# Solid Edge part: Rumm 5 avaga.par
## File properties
Title: Wasserdichte Bremsnabe
Author: Kadik
Comments: F200 112x5 - M12x1,5
Template: Normál.par
Last saved by: Kadik
Revision: 34
Application: Solid Edge
Material: GG25 (HB 195-225)
Category: 6A2267.001
Density: 7850,000 kg/m^3
Accuracy: 0,99
Document Number: 6A5139
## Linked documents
6A0073.001.par
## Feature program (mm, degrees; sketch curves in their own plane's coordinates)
part copy "unnamed PartCopy 1"
sketch for "unnamed RevolvedCutout 1" plane through (0, 0, 0) normal (0, -1, 0) x-axis (1, 0, 0)
  line (84.5, 117.2106) -> (84.5, 100)
  line (30.5, 100) -> (84.5, 100)
  line (30.5, 100) -> (20.5, 82.6795)
  line (20.5, 82.6795) -> (34.9125, 82.6795)
revolve "unnamed RevolvedCutout 1" cut full turn 360 deg
sketch for "unnamed RevolvedCutout 2" plane through (0, 0, 0) normal (0, -1, 0) x-axis (1, 0, 0)
  line (52, 32) -> (-14.4342, 32)
  line (52, 28) -> (52, 32)
  line (61, 28) -> (52, 28)
  line (61, 48.9983) -> (61, 28)
  line (61, 48.9983) -> (64.6809, 48.9983)
revolve "unnamed RevolvedCutout 2" cut full turn 360 deg
sketch for "unnamed RevolvedCutout 3" plane through (0, 0, 0) normal (0, -1, 0) x-axis (1, 0, 0)
  line (52, 32.2714) -> (50, 32)
  line (52, 32.2714) -> (52, 28)
revolve "unnamed RevolvedCutout 3" cut full turn 360 deg
sketch for "unnamed RevolvedCutout 4" plane through (0, 0, 0) normal (0, -1, 0) x-axis (1, 0, 0)
  line (0, 0) -> (0, 0)
  line (11, 32) -> (11, 33.3319)
  arc centre (11.5, 33.3319) radius 0.5 from (11, 33.3319) to (11.671, 33.8017) cw
  line (12.5, 33.5) -> (11.671, 33.8017)
  line (12.5, 33.5) -> (13.65, 33.5)
  line (13.65, 33.5) -> (14.479, 33.8017)
  arc centre (14.65, 33.3319) radius 0.5 from (14.479, 33.8017) to (15.15, 33.3319) cw
  line (15.15, 32.05) -> (15.15, 33.3319)
revolve "unnamed RevolvedCutout 4" cut full turn 360 deg
sketch for "unnamed RevolvedCutout 5" plane through (0, 0, 0) normal (0, -1, 0) x-axis (1, 0, 0)
  line (13.7186, 32.05) -> (13.7186, 30.6211)
  line (13.7186, 32.05) -> (5.8, 32.05)
  arc centre (5.8, 33.05) radius 1 from (4.8, 33.05) to (5.8, 32.05) ccw
  line (4.8, 33.1608) -> (4.8, 33.05)
  arc centre (4.3, 33.1608) radius 0.5 from (4.55, 33.5938) to (4.8, 33.1608) cw
  line (3.5, 34.2) -> (4.55, 33.5938)
  line (3.5, 34.5) -> (3.5, 34.2)
  arc centre (3, 34.5) radius 0.5 from (3, 35) to (3.5, 34.5) cw
  line (2, 35) -> (3, 35)
  line (1.5, 35.5) -> (2, 35)
  line (1.5, 64.6191) -> (1.5, 35.5)
revolve "unnamed RevolvedCutout 5" cut full turn 360 deg
sketch for "unnamed RevolvedCutout 6" plane through (0, 0, 0) normal (0, -1, 0) x-axis (1, 0, 0)
revolve "unnamed RevolvedCutout 6" cut full turn 360 deg
fillet "unnamed Round 1"
chamfer "Letörés_2" setback 0.2
fillet "unnamed Round 2"
sketch for "unnamed RevolvedCutout 7" plane through (0, 0, 0) normal (0, -1, 0) x-axis (1, 0, 0)
revolve "unnamed RevolvedCutout 7" cut full turn 360 deg
chamfer "Chamfer_3" setback 1
sketch for "Hole_1" plane through (1.5, 0, 0) normal (-1, 0, 0) x-axis (0, -1, 0)
hole "Hole_1" diameter 12 through  CounterSinkAngle = 120 deg
pattern "unnamed Pattern 1" of "Hole_1"
hole "unnamed Hole 1" through
hole "unnamed Hole 2" through
hole "unnamed Hole 3" through
hole "unnamed Hole 4" through
sketch for "ExtrudedProtrusion_1" #1 plane through (84.5, 0, 0) normal (1, 0, 0) x-axis (0, 1, 0)
sketch for "ExtrudedProtrusion_1" #2 plane through (84.5, 0, 0) normal (1, 0, 0) x-axis (0, 1, 0)
extrude "ExtrudedProtrusion_1" add finite 20 along +normal
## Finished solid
Body 1: solid body, 65 faces, 70 edges, 0 vertices.
  Faces by surface: cone 21, torus 19, cylinder 15, plane 10
  Edges by curve: circle 65, intersection 5
Bounding box of the edges (mm; curved faces can reach further): 103.000 x 226.000 x 226.000, from (1.5, -113, -113) to (104.5, 113, 113).
Cylindrical faces by radius (mm): R5.25 x5, R28 x1, R32 x1, R32.05 x1, R33.5 x1, R35 x1, R91 x1, R100 x1, R101 x1, R105.2512 x1, R113 x1
Conical faces (half-angle, radius in mm at the cone's reference point): 1.3172 deg R107.208 x1, 1.5 deg R98.5 x1, 3 deg R43.745 x1, 3 deg R106.0241 x1, 7.7282 deg R32 x1, 10 deg R28 x1, 20 deg R33.5 x1, 20 deg R33.8017 x1, 30 deg R33.5938 x1, 32.7023 deg R90.4356 x1, 45 deg R28 x1, 45 deg R35 x1, 45 deg R101 x1, 50 deg R91 x1, 50 deg R93.0021 x1, 60 deg R6.25 x5, 60 deg R100 x1
Toroidal faces (ring radius, tube radius in mm): R31.699 r0.5 x1, R33.05 r1 x1, R33.1608 r0.5 x1, R33.3319 r0.5 x2, R33.9593 r9 x1, R34.5 r0.5 x1, R67.7121 r24 x1, R72.4892 r10 x1, R83.0249 r10 x1, R85.9315 r11 x1, R87.2133 r20 x1, R95 r4 x1, R98 r2 x1, R102.6531 r3 x1, R107.4475 r1.5 x1, R110.5 r2.5 x1, R110.5831 r2.5 x1, R111.5 r1.5 x1
Planar faces by outward normal: +x 5, -x 5
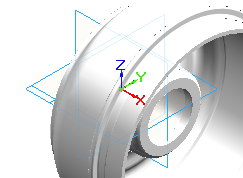
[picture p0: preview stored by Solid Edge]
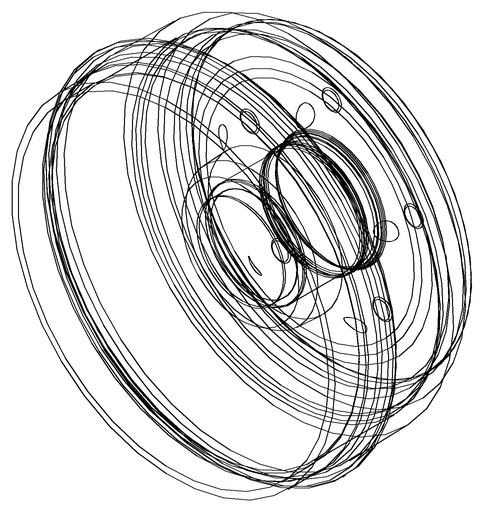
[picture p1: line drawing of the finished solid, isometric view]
